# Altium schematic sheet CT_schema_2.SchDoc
size 283 x 135 mm
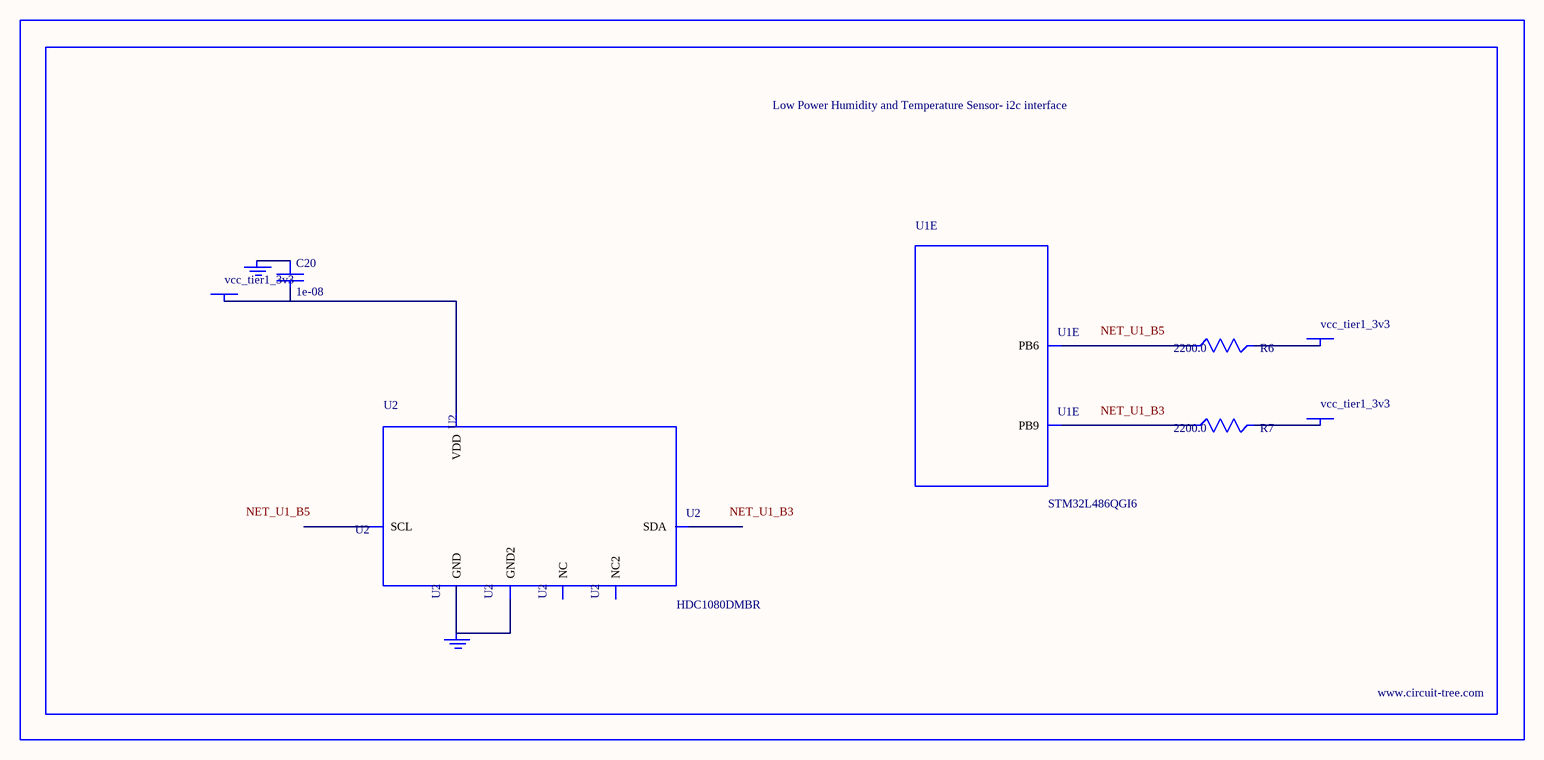
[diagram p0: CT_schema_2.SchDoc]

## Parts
BORDER1  (no value)
C20  1e-08  [C0402]
GND_INSTANCE_1_0  (no value)
GND_INSTANCE_1_1  (no value)
POWER_INSTANCE_1_0  vcc_tier1_3v3
POWER_INSTANCE_1_1  vcc_tier1_3v3
POWER_INSTANCE_1_2  vcc_tier1_3v3
R6  2200.0  [R0603]
R7  2200.0  [R0603]
U1  STM32L486QGI6  [UFBGA132]  (part E of 13)
U2  HDC1080DMBR  [WSON-6]

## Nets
NetC20_1: C20.1 GND_INSTANCE_1_0.0(GND)
NetC20_2: C20.2 POWER_INSTANCE_1_0.0(PWR) U2.5(VDD)
NetGND_INSTANCE_1_1_0: GND_INSTANCE_1_1.0(GND) U2.2(GND) U2.PAD(GND2)
NetPOWER_INSTANCE_1_1_0: POWER_INSTANCE_1_1.0(PWR) R6.2
NetPOWER_INSTANCE_1_2_0: POWER_INSTANCE_1_2.0(PWR) R7.2
NetR6_1: R6.1 U1.B5(PB6)
NetR7_1: R7.1 U1.B3(PB9)

Not connected (* = marked no-connect by the designer): U2 1(SDA) 3(NC) 4(NC2) 6(SCL)

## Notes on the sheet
- Labels drawn without touching a wire or pin: NET_U1_B3, NET_U1_B5

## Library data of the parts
BORDER1 = BORDER_PAGE1
C20 = C0402C103K3RAC
GND_INSTANCE_1_0 GND_INSTANCE_1_1 = GND
POWER_INSTANCE_1_0-POWER_INSTANCE_1_2 = PWR
R6 R7 = RC0603JR-072K2L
